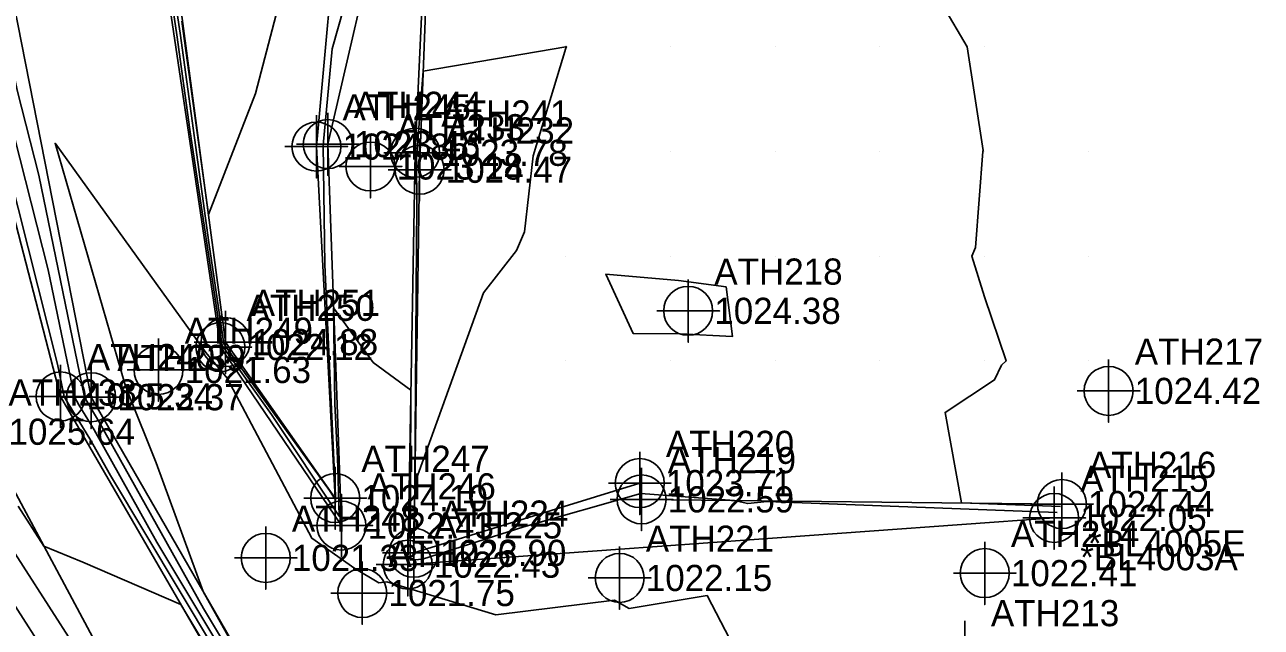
# Model space of a CAD drawing. Extents: x 1213164 to 1213550, y 766120 to 766870.
# Drawn here: x 1213428.3 to 1213546.5, y 766234.6 to 766292.1 of the extents above; entities that cross this region are included whole.
import ezdxf

# ---------------------------------------------------------------- set-up
doc = ezdxf.new("R2010")
doc.units = 0
for name, color, linetype in [('Default', 7, 'Continuous'), ('Exist DTM Breakline', 7, 'Continuous'), ('Exist DTM Breakline Cogo Comment', 7, 'Continuous'), ('Exist DTM Breakline Cogo Elevation', 7, 'Continuous'), ('Exist DTM Breakline Cogo Number', 7, 'Continuous'), ('Exist DTM Breakline Cogo Point CELL', 7, 'Continuous'), ('Exist DTM Drainline Cogo Comment', 7, 'Continuous'), ('Exist DTM Drainline Cogo Elevation', 7, 'Continuous'), ('Exist DTM Drainline Cogo Number', 7, 'Continuous'), ('Exist DTM Drainline Cogo Point CELL', 7, 'Continuous'), ('Exist DTM QL2 LIDAR Elevation Point', 7, 'Continuous'), ('Exist DTM Regular Point CELL', 7, 'Continuous'), ('Exist DTM Regular Point Cogo Elevation', 7, 'Continuous'), ('Exist DTM Regular Point Cogo Number', 7, 'Continuous'), ('Exist DTM Regular Point Underwater CELL', 7, 'Continuous'), ('Exist DTM Regular Point Underwater Cogo Elevation', 7, 'Continuous'), ('Exist DTM Regular Point Underwater Cogo Number', 7, 'Continuous'), ('Exist Hydro Stream or Body of Water', 7, 'Continuous'), ('Exist Roads EOP', 7, 'Continuous')]:
    doc.layers.add(name, color=color, linetype=linetype)

msp = doc.modelspace()

# ---------------------------------------------------------------- linework, layer by layer
at = {"layer": 'Default'}
for points in [[(1213420.06, 766304.95), (1213424.27, 766288.24), (1213424.81, 766285.7), (1213431.4, 766259.7), (1213432.04, 766256.61), (1213432.14, 766256.42), (1213434.49, 766252.57), (1213436.46, 766249.05), (1213449.69, 766226.99), (1213451.6, 766226.92), (1213452.21, 766226.91), (1213473.09, 766226.2), (1213482.19, 766226.05), (1213483.85, 766226.26), (1213496.25, 766220.26), (1213501.96, 766221.57), (1213508.68, 766214.24)], [(1213442.15, 766297.8), (1213443.12, 766291.32), (1213445.87, 766271.31), (1213447.31, 766261.65), (1213457.4, 766247.62), (1213457.98, 766246.74), (1213457.97, 766247.16), (1213457.82, 766250.56), (1213456.97, 766269.18), (1213456.8, 766280.63), (1213457.67, 766289.82), (1213461.64, 766303.9)], [(1213526.96, 766245.53), (1213499.23, 766246.57), (1213497.39, 766246.38), (1213496.09, 766246.68), (1213487.17, 766247.35), (1213475.98, 766244.14), (1213466.28, 766241.07), (1213465.11, 766240.98), (1213465.18, 766257.2), (1213461.58, 766259.84), (1213457.8, 766265.07), (1213457.93, 766255.92), (1213458.17, 766250.7), (1213458.21, 766249.75), (1213458.34, 766245.16), (1213451.87, 766254.9), (1213447.14, 766261.48), (1213444.05, 766282.13), (1213442.81, 766291.15), (1213441.02, 766303.14)], [(1213454.41, 766301.17), (1213450.33, 766285.56), (1213445.83, 766274), (1213443.43, 766291.5)], [(1213396.59, 766300.3), (1213401.19, 766291.42), (1213407.01, 766278.66), (1213411.88, 766267.99), (1213420.58, 766251.81), (1213423.73, 766246.95), (1213425.64, 766244.22), (1213440.38, 766221.3), (1213441.65, 766219.49), (1213441.73, 766219.33), (1213444.46, 766212.55), (1213448.66, 766204.27), (1213458.93, 766188.04), (1213458.45, 766186.29)], [(1213424.74, 766299.28), (1213427.56, 766285.88), (1213429.63, 766277.75), (1213434, 766256.55), (1213434.74, 766255.23), (1213435.33, 766254.27), (1213445.35, 766236.36), (1213450.26, 766228.16), (1213450.97, 766228.14), (1213452.49, 766228.12), (1213460.35, 766227.85), (1213482.44, 766227.49), (1213486.49, 766228.01), (1213491.53, 766225.56), (1213516.94, 766231.38), (1213519.02, 766229.11), (1213527.88, 766208.79)], [(1213395.96, 766296.87), (1213404.69, 766277.75), (1213411.99, 766261.76), (1213417.91, 766250.75), (1213420.05, 766247.45), (1213423.65, 766242.32), (1213433.86, 766226.44), (1213439.97, 766217.66), (1213440.36, 766216.9), (1213442.34, 766211.98), (1213448.67, 766199.5), (1213456.64, 766186.9), (1213456.04, 766184.72)], [(1213424.51, 766293.76), (1213426.19, 766285.79), (1213430.51, 766268.72), (1213433.02, 766256.58), (1213433.44, 766255.82), (1213434.91, 766253.42), (1213440.91, 766242.7), (1213449.98, 766227.57), (1213451.29, 766227.53), (1213452.35, 766227.51), (1213466.72, 766227.02), (1213482.31, 766226.77), (1213485.17, 766227.14), (1213493.89, 766222.91), (1213509.45, 766226.47), (1213524.7, 766209.84), (1213525.67, 766207.61)], [(1213516.04, 766293.96), (1213518.35, 766290), (1213519.9, 766280.1), (1213519.84, 766280), (1213519.16, 766270.84), (1213518.81, 766270), (1213520, 766266.12), (1213522.09, 766260), (1213521.63, 766259.61), (1213520.98, 766258.19), (1213516.25, 766255.09), (1213517.82, 766246.44), (1213527.27, 766246.09)], [(1213443.43, 766291.5), (1213443.29, 766292.46)], [(1213479.98, 766290.02), (1213480, 766290.06), (1213480.06, 766290), (1213480.04, 766289.96), (1213480, 766289.9), (1213476.86, 766279.61), (1213476.05, 766272.34), (1213475.27, 766270.56), (1213472.13, 766266.52), (1213465.56, 766248.34), (1213465.72, 766271.2), (1213465.74, 766274.68), (1213465.73, 766279.37), (1213466.37, 766287.7), (1213479.98, 766290.02)], [(1213449.79, 766230.01), (1213445.33, 766237.98), (1213440.85, 766250.28), (1213438.19, 766256.87), (1213437.83, 766257.83), (1213431.17, 766280.8), (1213445.58, 766260.81), (1213447.62, 766258.36)], [(1213495.32, 766267.07), (1213490.75, 766267.69), (1213483.82, 766268.3), (1213486.42, 766262.63), (1213490.91, 766262.59), (1213495.94, 766262.34), (1213495.32, 766267.07)], [(1213447.62, 766258.36), (1213455.7, 766243.06), (1213459.82, 766240.16), (1213462.13, 766238.82), (1213462.88, 766238.89), (1213473.3, 766235.75), (1213484.64, 766237.14), (1213486.05, 766236.36), (1213493.49, 766237.58), (1213497.4, 766230.1)], [(1213427.64, 766246.13), (1213430.09, 766242.32), (1213433.84, 766240.78), (1213443.2, 766236.75), (1213449.41, 766226.4), (1213451.91, 766226.31), (1213452.07, 766226.31), (1213479.46, 766225.38), (1213482.06, 766225.33), (1213482.53, 766225.39), (1213489.61, 766221.96), (1213485.85, 766218.36), (1213480.37, 766221.23), (1213472.26, 766221.72), (1213451.12, 766222.76), (1213449.13, 766222.86), (1213444.92, 766217.23), (1213446.58, 766213.11), (1213448.64, 766209.05), (1213461.22, 766189.17), (1213460.86, 766187.86)]]:
    msp.add_lwpolyline(points, dxfattribs=at)
at = {"layer": 'Exist DTM Breakline'}
for points in [[(1213458.36, 766304.67), (1213456.15, 766280.48), (1213457.95, 766246.9), (1213447.47, 766261.8), (1213441.28, 766307.97), (1213433.95, 766370.73), (1213403.81, 766386.39), (1213393.08, 766404.94), (1213391.08, 766440.45), (1213383.54, 766456.52), (1213369.39, 766482.2), (1213351.86, 766502.12)], [(1213525.39, 766207.47), (1213482.01, 766225.05), (1213449.3, 766226.19), (1213431.7, 766256.62), (1213419.18, 766304.88), (1213413.48, 766348.82), (1213382.31, 766373.43), (1213372.71, 766395.69), (1213369.18, 766434.58), (1213366.95, 766449.61), (1213359.43, 766466.81), (1213345.1, 766468.72)], [(1213468.09, 766192.57), (1213448.63, 766213.66), (1213442.08, 766219.96), (1213424.22, 766253.24), (1213401.52, 766302.49), (1213377.56, 766344.05), (1213361.4, 766370.67), (1213365.74, 766393.84)], [(1213527.41, 766246.33), (1213487.24, 766246.78), (1213487.06, 766248.33), (1213465.46, 766241.67), (1213466.02, 766278.27), (1213466.9, 766301.8)]]:
    msp.add_lwpolyline(points, dxfattribs=at)
at = {"layer": 'Exist DTM Breakline Cogo Point CELL'}
for points in [[(1213456.15, 766283.48), (1213456.15, 766277.48), (1213456.15, 766280.48), (1213459.15, 766280.48), (1213453.15, 766280.48)], [(1213466.02, 766281.27), (1213466.02, 766275.27), (1213466.02, 766278.27), (1213469.02, 766278.27), (1213463.02, 766278.27)], [(1213447.47, 766264.8), (1213447.47, 766258.8), (1213447.47, 766261.8), (1213450.47, 766261.8), (1213444.47, 766261.8)], [(1213431.7, 766259.62), (1213431.7, 766253.62), (1213431.7, 766256.62), (1213434.7, 766256.62), (1213428.7, 766256.62)], [(1213487.06, 766251.33), (1213487.06, 766245.33), (1213487.06, 766248.33), (1213490.06, 766248.33), (1213484.06, 766248.33)], [(1213457.95, 766249.9), (1213457.95, 766243.9), (1213457.95, 766246.9), (1213460.95, 766246.9), (1213454.95, 766246.9)], [(1213487.24, 766249.78), (1213487.24, 766243.78), (1213487.24, 766246.78), (1213490.24, 766246.78), (1213484.24, 766246.78)], [(1213527.41, 766249.33), (1213527.41, 766243.33), (1213527.41, 766246.33), (1213530.41, 766246.33), (1213524.41, 766246.33)], [(1213465.46, 766244.67), (1213465.46, 766238.67), (1213465.46, 766241.67), (1213468.46, 766241.67), (1213462.46, 766241.67)]]:
    msp.add_lwpolyline(points, dxfattribs=at)
for centre in [(1213456.15, 766280.48), (1213466.02, 766278.27), (1213447.47, 766261.8), (1213431.7, 766256.62), (1213487.06, 766248.33), (1213457.95, 766246.9), (1213487.24, 766246.78), (1213527.41, 766246.33), (1213465.46, 766241.67)]:
    msp.add_circle(centre, 2.34, dxfattribs=at)
at = {"layer": 'Exist DTM Drainline Cogo Point CELL'}
for points in [[(1213457.24, 766283.72), (1213457.24, 766277.72), (1213457.24, 766280.72), (1213460.24, 766280.72), (1213454.24, 766280.72)], [(1213465.59, 766282.89), (1213465.59, 766276.89), (1213465.59, 766279.89), (1213468.59, 766279.89), (1213462.59, 766279.89)], [(1213446.98, 766264.33), (1213446.98, 766258.33), (1213446.98, 766261.33), (1213449.98, 766261.33), (1213443.98, 766261.33)], [(1213434.62, 766259.54), (1213434.62, 766253.54), (1213434.62, 766256.54), (1213437.62, 766256.54), (1213431.62, 766256.54)], [(1213526.67, 766248), (1213526.67, 766242), (1213526.67, 766245), (1213529.67, 766245), (1213523.67, 766245)], [(1213458.54, 766247.27), (1213458.54, 766241.27), (1213458.54, 766244.27), (1213461.54, 766244.27), (1213455.54, 766244.27)], [(1213464.88, 766243.54), (1213464.88, 766237.54), (1213464.88, 766240.54), (1213467.88, 766240.54), (1213461.88, 766240.54)], [(1213518.13, 766235.16), (1213518.13, 766229.16), (1213518.13, 766232.16), (1213521.13, 766232.16), (1213515.13, 766232.16)]]:
    msp.add_lwpolyline(points, dxfattribs=at)
for centre in [(1213457.24, 766280.72), (1213465.59, 766279.89), (1213446.98, 766261.33), (1213434.62, 766256.54), (1213526.67, 766245), (1213458.54, 766244.27), (1213464.88, 766240.54)]:
    msp.add_circle(centre, 2.34, dxfattribs=at)
at = {"layer": 'Exist DTM QL2 LIDAR Elevation Point'}
for p, q in [((1213480, 766290), (1213480, 766290)), ((1213490, 766290), (1213490, 766290)), ((1213500, 766290), (1213500, 766290)), ((1213510, 766290), (1213510, 766290)), ((1213520, 766290), (1213520, 766290)), ((1213480, 766280), (1213480, 766280)), ((1213490, 766280), (1213490, 766280)), ((1213500, 766280), (1213500, 766280)), ((1213510, 766280), (1213510, 766280)), ((1213520, 766280), (1213520, 766280)), ((1213530, 766280), (1213530, 766280)), ((1213480, 766270), (1213480, 766270)), ((1213490, 766270), (1213490, 766270)), ((1213500, 766270), (1213500, 766270)), ((1213510, 766270), (1213510, 766270)), ((1213520, 766270), (1213520, 766270)), ((1213530, 766270), (1213530, 766270)), ((1213480, 766260), (1213480, 766260)), ((1213490, 766260), (1213490, 766260)), ((1213500, 766260), (1213500, 766260)), ((1213510, 766260), (1213510, 766260)), ((1213520, 766260), (1213520, 766260)), ((1213530, 766260), (1213530, 766260))]:
    msp.add_line(p, q, dxfattribs=at)
at = {"layer": 'Exist DTM Regular Point CELL'}
for points in [[(1213491.69, 766267.79), (1213491.69, 766261.79), (1213491.69, 766264.79), (1213494.69, 766264.79), (1213488.69, 766264.79)], [(1213531.88, 766260.14), (1213531.88, 766254.14), (1213531.88, 766257.14), (1213534.88, 766257.14), (1213528.88, 766257.14)]]:
    msp.add_lwpolyline(points, dxfattribs=at)
for centre in [(1213491.69, 766264.79), (1213531.88, 766257.14)]:
    msp.add_circle(centre, 2.34, dxfattribs=at)
at = {"layer": 'Exist DTM Regular Point Underwater CELL'}
for points in [[(1213461.32, 766281.58), (1213461.32, 766275.58), (1213461.32, 766278.58), (1213464.32, 766278.58), (1213458.32, 766278.58)], [(1213441.06, 766262.14), (1213441.06, 766256.14), (1213441.06, 766259.14), (1213444.06, 766259.14), (1213438.06, 766259.14)], [(1213451.31, 766244.19), (1213451.31, 766238.19), (1213451.31, 766241.19), (1213454.31, 766241.19), (1213448.31, 766241.19)], [(1213485.14, 766242.27), (1213485.14, 766236.27), (1213485.14, 766239.27), (1213488.14, 766239.27), (1213482.14, 766239.27)], [(1213520.04, 766242.73), (1213520.04, 766236.73), (1213520.04, 766239.73), (1213523.04, 766239.73), (1213517.04, 766239.73)], [(1213460.54, 766240.83), (1213460.54, 766234.83), (1213460.54, 766237.83), (1213463.54, 766237.83), (1213457.54, 766237.83)]]:
    msp.add_lwpolyline(points, dxfattribs=at)
for centre in [(1213461.32, 766278.58), (1213441.06, 766259.14), (1213451.31, 766241.19), (1213520.04, 766239.73), (1213485.14, 766239.27), (1213460.54, 766237.83)]:
    msp.add_circle(centre, 2.34, dxfattribs=at)
at = {"layer": 'Exist Hydro Stream or Body of Water'}
for points in [[(1213462.58, 766303.68), (1213457.24, 766280.72), (1213458.54, 766244.27), (1213446.98, 766261.33), (1213440.13, 766307.33), (1213429.65, 766367.83), (1213400.18, 766384.29), (1213389.88, 766405.51), (1213387.13, 766439.71), (1213382.82, 766456.43), (1213368.02, 766480.63), (1213349.52, 766498.12), (1213324.24, 766505.78)], [(1213528.18, 766208.95), (1213518.13, 766232.16), (1213482.65, 766228.64), (1213450.6, 766228.86), (1213434.62, 766256.54), (1213425, 766305.33), (1213420.53, 766356.32), (1213385.1, 766376.62), (1213376.32, 766397.22), (1213374.29, 766436.33), (1213371.57, 766451.85), (1213360.53, 766468.46), (1213342.81, 766469.47)], [(1213526.67, 766245), (1213464.88, 766240.54), (1213465.59, 766279.89), (1213466.65, 766302.51)]]:
    msp.add_lwpolyline(points, dxfattribs=at)
at = {"layer": 'Exist Roads EOP'}
msp.add_spline([(1213405.88, 766244.7), (1213426.93, 766208.86), (1213432.41, 766199.22), (1213442.58, 766180.07)], degree=3, dxfattribs=at)

# ---------------------------------------------------------------- texts
at = {"layer": 'Exist DTM Breakline Cogo Comment'}
msp.add_text('*BL4005E', height=2.5, dxfattribs=at).set_placement((1213529.91, 766241.33))
at = {"layer": 'Exist DTM Breakline Cogo Elevation'}
for s, p in [('1024.85', (1213458.65, 766279.23)), ('1024.47', (1213468.52, 766277.02)), ('1024.88', (1213449.97, 766260.55)), ('1025.34', (1213434.2, 766255.37)), ('1025.64', (1213426.72, 766251.99)), ('1023.71', (1213489.56, 766247.08)), ('1024.10', (1213460.45, 766245.65)), ('1022.59', (1213489.74, 766245.53)), ('1024.44', (1213529.91, 766245.08)), ('1023.90', (1213467.96, 766240.42))]:
    msp.add_text(s, height=2.5, dxfattribs=at).set_placement(p)
at = {"layer": 'Exist DTM Breakline Cogo Number'}
for s, p in [('ATH245', (1213458.65, 766282.98)), ('ATH232', (1213468.52, 766280.77)), ('ATH251', (1213449.97, 766264.3)), ('ATH240', (1213434.2, 766259.12)), ('ATH238', (1213426.72, 766255.74)), ('ATH220', (1213489.56, 766250.83)), ('ATH247', (1213460.45, 766249.4)), ('ATH219', (1213489.74, 766249.28)), ('ATH216', (1213529.91, 766248.83)), ('ATH224', (1213467.96, 766244.17))]:
    msp.add_text(s, height=2.5, dxfattribs=at).set_placement(p)
at = {"layer": 'Exist DTM Drainline Cogo Comment'}
msp.add_text('*BL4003A', height=2.5, dxfattribs=at).set_placement((1213529.17, 766240))
at = {"layer": 'Exist DTM Drainline Cogo Elevation'}
for s, p in [('1023.43', (1213459.74, 766279.47)), ('1023.78', (1213468.09, 766278.64)), ('1022.12', (1213449.48, 766260.08)), ('1022.37', (1213437.12, 766255.29)), ('1022.05', (1213529.17, 766243.75)), ('1022.43', (1213461.04, 766243.02)), ('1022.43', (1213467.38, 766239.29))]:
    msp.add_text(s, height=2.5, dxfattribs=at).set_placement(p)
at = {"layer": 'Exist DTM Drainline Cogo Number'}
for s, p in [('ATH244', (1213459.74, 766283.22)), ('ATH241', (1213468.09, 766282.39)), ('ATH250', (1213449.48, 766263.83)), ('ATH239', (1213437.12, 766259.04)), ('ATH246', (1213461.04, 766246.77)), ('ATH215', (1213529.17, 766247.5)), ('ATH225', (1213467.38, 766243.04)), ('ATH213', (1213520.63, 766234.66))]:
    msp.add_text(s, height=2.5, dxfattribs=at).set_placement(p)
at = {"layer": 'Exist DTM Regular Point Cogo Elevation'}
for s, p in [('1024.38', (1213494.19, 766263.54)), ('1024.42', (1213534.38, 766255.89))]:
    msp.add_text(s, height=2.5, dxfattribs=at).set_placement(p)
at = {"layer": 'Exist DTM Regular Point Cogo Number'}
for s, p in [('ATH218', (1213494.19, 766267.29)), ('ATH217', (1213534.38, 766259.64))]:
    msp.add_text(s, height=2.5, dxfattribs=at).set_placement(p)
at = {"layer": 'Exist DTM Regular Point Underwater Cogo Elevation'}
for s, p in [('1023.18', (1213463.82, 766277.33)), ('1021.63', (1213443.56, 766257.89)), ('1021.33', (1213453.81, 766239.94)), ('1022.41', (1213522.54, 766238.48)), ('1022.15', (1213487.64, 766238.02)), ('1021.75', (1213463.04, 766236.58))]:
    msp.add_text(s, height=2.5, dxfattribs=at).set_placement(p)
at = {"layer": 'Exist DTM Regular Point Underwater Cogo Number'}
for s, p in [('ATH233', (1213463.82, 766281.08)), ('ATH249', (1213443.56, 766261.64)), ('ATH248', (1213453.81, 766243.69)), ('ATH214', (1213522.54, 766242.23)), ('ATH221', (1213487.64, 766241.77)), ('ATH226', (1213463.04, 766240.33))]:
    msp.add_text(s, height=2.5, dxfattribs=at).set_placement(p)

doc.saveas('drawing.dxf')
